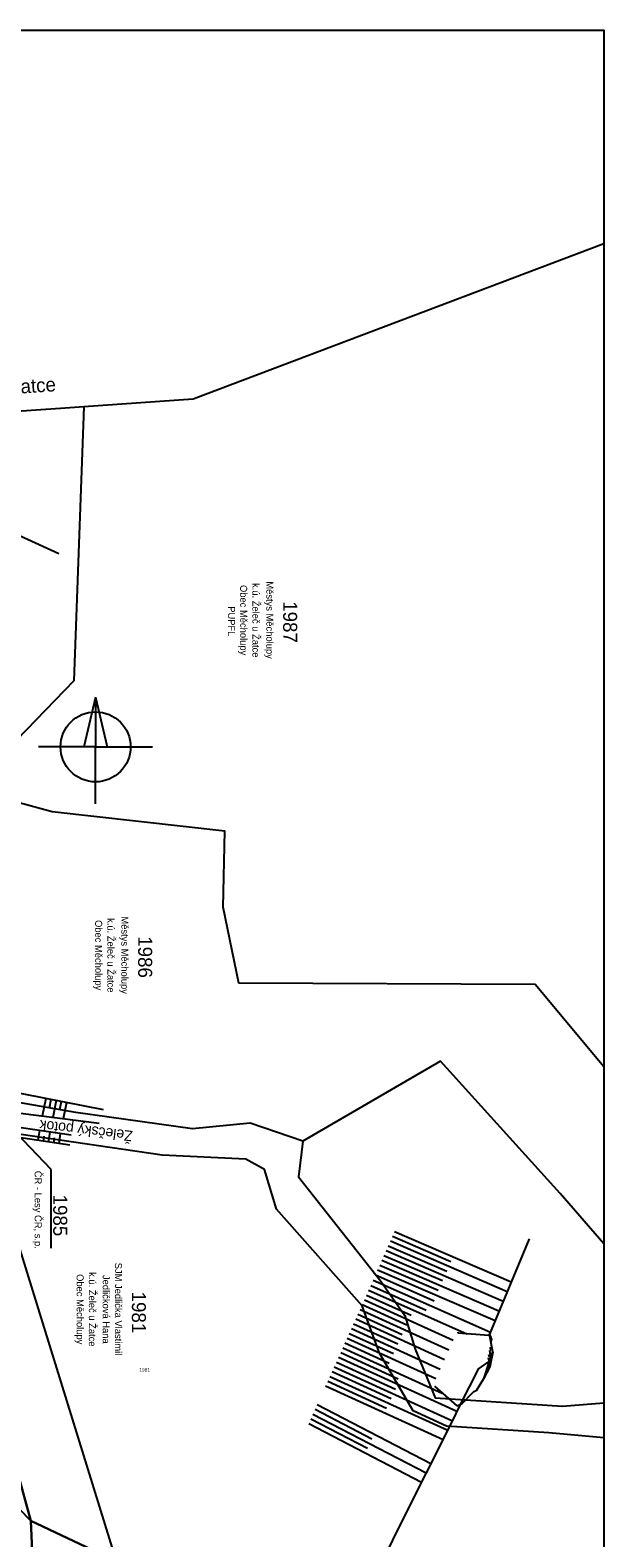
# Model space of a CAD drawing. Extents: x -801372 to -800991, y -1017235 to -1016862.
# Drawn here: x -801072.7 to -800990.8, y -1017121 to -1016905.7 of the extents above; entities that cross this region are included whole.
import ezdxf

# ---------------------------------------------------------------- set-up
doc = ezdxf.new("R2010")
doc.units = 0
for name, color, linetype in [('09 - stávající terén', 7, 'Continuous'), ('13b - kóty bílé', 7, 'Continuous'), ('15 - popisy', 7, 'Continuous'), ('19 - katastr', 7, 'Continuous'), ('19b - katastr - hranice SŽDC', 7, 'Continuous'), ('19b - katastr popisy', 7, 'Continuous'), ('23 - neviditelná', 7, 'Continuous'), ('26 - obvod_stavby', 7, 'Continuous'), ('27 - dočasné zábory', 7, 'Continuous'), ('Vrstva 48 - svahy', 7, 'Continuous'), ('Vrstva 55 - k.ú.', 7, 'Continuous'), ('Vrstva 58', 7, 'Continuous')]:
    doc.layers.add(name, color=color, linetype=linetype)

# ---------------------------------------------------------------- blocks, each defined once
blk = doc.blocks.new('SEVERKA')
at = {"layer": '15 - popisy'}
for p, q in [((0, 1.418), (-0.333, 0)), ((0, 1.418), (0.333, 0)), ((0, 1.418), (0, 0)), ((0, 0), (-1.625, 0)), ((0, 0), (1.625, 0)), ((0, -1.625), (0, 0))]:
    blk.add_line(p, q, dxfattribs=at)
blk.add_circle((0, 0), 1, dxfattribs=at)

msp = doc.modelspace()

# ---------------------------------------------------------------- linework, layer by layer
for points in [[(-801079.49, -1017062.75), (-801060.39, -1017124.37)], [(-801086.97, -1017066.29), (-801072.61, -1017118.61)], [(-801072.61, -1017118.61), (-801071.85, -1017135.76)]]:
    msp.add_lwpolyline(points)
at = {"layer": '09 - stávající terén'}
for p, q in [((-801084.74, -1016973.11), (-801068.6, -1016980.41)), ((-801062.23, -1017059.89), (-801076.49, -1017057.08)), ((-801062.82, -1017061.84), (-801077.12, -1017060.06)), ((-801067.03, -1017064.95), (-801083.83, -1017062.45)), ((-801066.83, -1017063.53), (-801082.64, -1017061.2)), ((-801001.45, -1017078.32), (-801007.12, -1017091.97)), ((-801011.58, -1017091.8), (-801011.58, -1017091.67)), ((-801007.23, -1017092.13), (-801011.58, -1017091.8)), ((-801007.12, -1017091.97), (-801007.23, -1017092.13)), ((-801006.64, -1017094.53), (-801007.12, -1017091.97)), ((-801007.12, -1017091.97), (-801006.85, -1017092.71)), ((-801006.85, -1017092.71), (-801006.91, -1017093.1)), ((-801007.18, -1017095.85), (-801006.64, -1017094.53)), ((-801006.64, -1017094.53), (-801007.06, -1017096.61)), ((-801008.71, -1017096.95), (-801011.31, -1017102)), ((-801008.71, -1017096.95), (-801007.18, -1017095.85)), ((-801007.18, -1017095.85), (-801007.96, -1017098.34)), ((-801007.06, -1017096.61), (-801007.96, -1017098.34)), ((-801007.15, -1017095.77), (-801007.26, -1017095.31)), ((-801007.06, -1017096.61), (-801007.15, -1017095.77)), ((-801007.96, -1017098.34), (-801009.03, -1017100.06)), ((-801014.99, -1017099.37), (-801011.78, -1017102.2)), ((-801011.11, -1017101.94), (-801009.43, -1017100.25)), ((-801009.03, -1017100.06), (-801009.43, -1017100.25)), ((-801011.31, -1017102), (-801012.52, -1017104.57)), ((-801011.78, -1017102.19), (-801011.31, -1017102)), ((-801011.78, -1017102.2), (-801011.78, -1017102.19)), ((-801011.31, -1017102), (-801011.05, -1017101.82)), ((-801011.05, -1017101.82), (-801011.11, -1017101.94)), ((-801012.52, -1017104.57), (-801019.85, -1017119.16)), ((-801019.85, -1017119.16), (-801024.33, -1017128.18))]:
    msp.add_line(p, q, dxfattribs=at)
at = {"layer": '19 - katastr'}
msp.add_line((-801065.05, -1016959.48), (-801068.35, -1016959.71), dxfattribs=at)
for points in [[(-800990.79, -1017053.76), (-801000.61, -1017041.98), (-801042.92, -1017041.79), (-801045.15, -1017030.95), (-801044.91, -1017020.07), (-801069.54, -1017017.32), (-801081.43, -1017014.11)], [(-800990.79, -1017079.04), (-800997.04, -1017071.83), (-801014.12, -1017052.97), (-801033.76, -1017064.4)], [(-801033.76, -1017064.4), (-801041.29, -1017061.79), (-801049.51, -1017062.6), (-801066.15, -1017060.28), (-801082.88, -1017057.4)], [(-800990.79, -1017106.78), (-800998.64, -1017106.06), (-801013.25, -1017105.09), (-801017.99, -1017102.9), (-801022.81, -1017094.66), (-801025.28, -1017087.9), (-801037.51, -1017074.11), (-801039.25, -1017068.41), (-801041.9, -1017066.94), (-801053.83, -1017066.4), (-801073.95, -1017063.41), (-801085.03, -1017062.08)], [(-801033.76, -1017064.4), (-801034.38, -1017069.49), (-801022.63, -1017084.37), (-801019.21, -1017089.27), (-801017.73, -1017094.07), (-801014.89, -1017101.06), (-800996.7, -1017102.24), (-800990.79, -1017101.76)], [(-801077.69, -1017113.44), (-801072.61, -1017118.61), (-801060.39, -1017124.37), (-801036.16, -1017131.43), (-801018.45, -1017131.86), (-801012.13, -1017133.6)]]:
    msp.add_lwpolyline(points, dxfattribs=at)
at = {"layer": '19b - katastr - hranice SŽDC'}
msp.add_lwpolyline([(-801065.05, -1016959.48), (-801066.45, -1016998.62), (-801081.43, -1017014.11)], dxfattribs=at)
at = {"layer": '19b - katastr popisy'}
for p, q in [((-801069.69, -1017068.41), (-801076.66, -1017061.13)), ((-801069.69, -1017079.67), (-801069.69, -1017068.41))]:
    msp.add_line(p, q, dxfattribs=at)
at = {"layer": '23 - neviditelná'}
msp.add_lwpolyline([(-801217.95, -1016905.67), (-800990.79, -1016905.67), (-800990.79, -1017234.77), (-801217.95, -1017234.77)], close=True, dxfattribs=at)
at = {"layer": '26 - obvod_stavby'}
msp.add_lwpolyline([(-801085, -1017062.08), (-801079.49, -1017062.75), (-801060.39, -1017124.37), (-801060.39, -1017137.35), (-801071.85, -1017135.76), (-801072.61, -1017118.61), (-801086.97, -1017066.29), (-801086.64, -1017070.52), (-801095.48, -1017082.49), (-801141.22, -1017053.25), (-801148.66, -1017042.44), (-801151.48, -1017039.58)], dxfattribs=at)
at = {"layer": '27 - dočasné zábory'}
for points in [[(-801072.61, -1017118.61), (-801086.97, -1017066.29), (-801085.03, -1017062.08), (-801079.49, -1017062.75), (-801060.39, -1017124.37), (-801072.61, -1017118.61)], [(-801072.61, -1017118.61), (-801060.39, -1017124.37), (-801060.39, -1017137.35), (-801071.85, -1017135.76), (-801072.61, -1017118.61)]]:
    msp.add_lwpolyline(points, dxfattribs=at)
at = {"layer": 'Vrstva 48 - svahy'}
for p, q in [((-801070.46, -1017058.27), (-801070.96, -1017060.83)), ((-801069.72, -1017058.41), (-801069.97, -1017059.67)), ((-801068.99, -1017058.56), (-801069.47, -1017061.01)), ((-801068.25, -1017058.7), (-801068.49, -1017059.9)), ((-801067.51, -1017058.85), (-801067.98, -1017061.2)), ((-801071.54, -1017064.28), (-801071.33, -1017062.87)), ((-801070.8, -1017064.39), (-801070.69, -1017063.68)), ((-801070.06, -1017064.5), (-801069.85, -1017063.09)), ((-801069.32, -1017064.61), (-801069.21, -1017063.9)), ((-801068.57, -1017064.72), (-801068.36, -1017063.31)), ((-801020.67, -1017077.26), (-801004, -1017084.46)), ((-801021.58, -1017079.32), (-801013.22, -1017082.93)), ((-801021.27, -1017078.63), (-801004.58, -1017085.85)), ((-801020.97, -1017077.95), (-801012.63, -1017081.55)), ((-801022.48, -1017081.38), (-801005.76, -1017088.61)), ((-801022.18, -1017080.69), (-801013.83, -1017084.3)), ((-801021.88, -1017080.01), (-801005.15, -1017087.24)), ((-801023.41, -1017083.49), (-801015.03, -1017087.17)), ((-801023.09, -1017082.75), (-801006.31, -1017090.01)), ((-801022.78, -1017082.07), (-801014.43, -1017085.68)), ((-801024.37, -1017085.67), (-801010.33, -1017091.89)), ((-801024.07, -1017084.98), (-801016.17, -1017088.52)), ((-801023.74, -1017084.24), (-801006.99, -1017091.65)), ((-801025.59, -1017088.41), (-801012.91, -1017094.2)), ((-801025.28, -1017087.73), (-801018.94, -1017090.62)), ((-801024.98, -1017087.04), (-801012.29, -1017092.82)), ((-801024.67, -1017086.36), (-801018.32, -1017089.24)), ((-801026.51, -1017090.46), (-801020.18, -1017093.35)), ((-801026.21, -1017089.78), (-801013.54, -1017095.56)), ((-801025.9, -1017089.09), (-801019.56, -1017091.99)), ((-801027.44, -1017092.51), (-801014.78, -1017098.29)), ((-801027.13, -1017091.83), (-801020.8, -1017094.72)), ((-801026.82, -1017091.15), (-801014.16, -1017096.93)), ((-801028.36, -1017094.57), (-801020.14, -1017098.32)), ((-801028.05, -1017093.88), (-801013.87, -1017100.36)), ((-801027.75, -1017093.2), (-801021.42, -1017096.09)), ((-801007.11, -1017095.17), (-801007.19, -1017094.86)), ((-801006.91, -1017095.19), (-801007.09, -1017094.26)), ((-801006.88, -1017094.29), (-801007.02, -1017093.8)), ((-801029.29, -1017096.62), (-801012.4, -1017104.32)), ((-801028.98, -1017095.93), (-801020.53, -1017099.79)), ((-801028.67, -1017095.25), (-801011.77, -1017102.97)), ((-801030.21, -1017098.67), (-801021.81, -1017102.5)), ((-801029.9, -1017097.99), (-801013.07, -1017105.67)), ((-801029.59, -1017097.3), (-801021.16, -1017101.15)), ((-801030.52, -1017099.35), (-801013.74, -1017107.01)), ((-801032.32, -1017103.36), (-801016.14, -1017111.78)), ((-801032.01, -1017102.68), (-801023.91, -1017106.89)), ((-801031.7, -1017102), (-801015.47, -1017110.44)), ((-801032.93, -1017104.73), (-801016.81, -1017113.11)), ((-801032.62, -1017104.05), (-801024.55, -1017108.25))]:
    msp.add_line(p, q, dxfattribs=at)
at = {"layer": 'Vrstva 55 - k.ú.'}
msp.add_lwpolyline([(-800990.79, -1016936.17), (-801049.4, -1016958.4), (-801065.05, -1016959.48), (-801068.35, -1016959.71), (-801098.33, -1016961.78)], dxfattribs=at)

# ---------------------------------------------------------------- block references
at = {"layer": '13b - kóty bílé', "xscale": 5, "yscale": 5}
msp.add_blockref('SEVERKA', (-801063.35, -1017008.05), dxfattribs=at)

# ---------------------------------------------------------------- texts
at = {"layer": '19b - katastr popisy'}
for s, height, p in [('Obec Měcholupy', 1.0001, (-801042.71, -1016984.93)), ('k.ú. Želeč u Žatce ', 1.0001, (-801040.96, -1016984.65)), ('Městys Měcholupy', 1.0001, (-801038.97, -1016984.4)), ('PUPFL', 1, (-801044.44, -1016987.96)), ('1987', 2, (-801036.57, -1016987.24)), ('Městys Měcholupy', 1.0001, (-801059.67, -1017032.27)), ('Obec Měcholupy', 1.0001, (-801063.41, -1017032.79)), ('k.ú. Želeč u Žatce ', 1.0001, (-801061.66, -1017032.52)), ('1986', 2, (-801057.27, -1017035.1)), ('ČR - Lesy ČR, s.p.', 1.0001, (-801072.05, -1017068.61)), ('1985', 2, (-801069.4, -1017072.01)), ('SJM Jedlička Vlastimil', 1.0001, (-801060.59, -1017081.74)), ('Obec Měcholupy', 1.0001, (-801066.06, -1017083.37)), ('k.ú. Želeč u Žatce ', 1.0001, (-801064.31, -1017083.09)), ('Jedličková Hana', 1.0001, (-801062.33, -1017083.49)), ('1981', 2, (-801058.17, -1017085.87))]:
    msp.add_text(s, height=height, rotation=270, dxfattribs=at).set_placement(p)
msp.add_text('1981', height=0.5, dxfattribs=at).set_placement((-801057.11, -1017097.3))
at = {"layer": 'Vrstva 55 - k.ú.'}
msp.add_text('k.ú. Mecholupy u Žatce', height=2, rotation=3.9498, dxfattribs=at).set_placement((-801096.54, -1016959.14))
at = {"layer": 'Vrstva 58'}
msp.add_text('Želečský potok', height=1.5, rotation=173.2137, dxfattribs=at).set_placement((-801057.99, -1017062.93))

doc.saveas('drawing.dxf')
